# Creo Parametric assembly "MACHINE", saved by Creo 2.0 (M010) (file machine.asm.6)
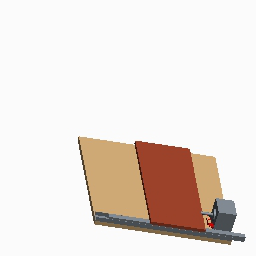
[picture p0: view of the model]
Units: Inch lbm Second (Pro/E Default); INCH, POUND, SECS

Created from: INLBS_ASM_DESIGN.ASM

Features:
  1. datum plane "ASM_RIGHT"
  2. datum plane "ASM_TOP"
  3. datum plane "ASM_FRONT"
  4. coordinate system
  5. component "BASE_BOARD"
  6. component "TOPBOARD"
  7. component "YMOTOR"
  8. component "MOTOR"
  9. component "PRT0001"
  10. component "SLIDE_TOP"

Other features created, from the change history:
  component "YMOTOR.PRT"
  component "BASE_BOARD.PRT"
  component "TOPBOARD.PRT"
